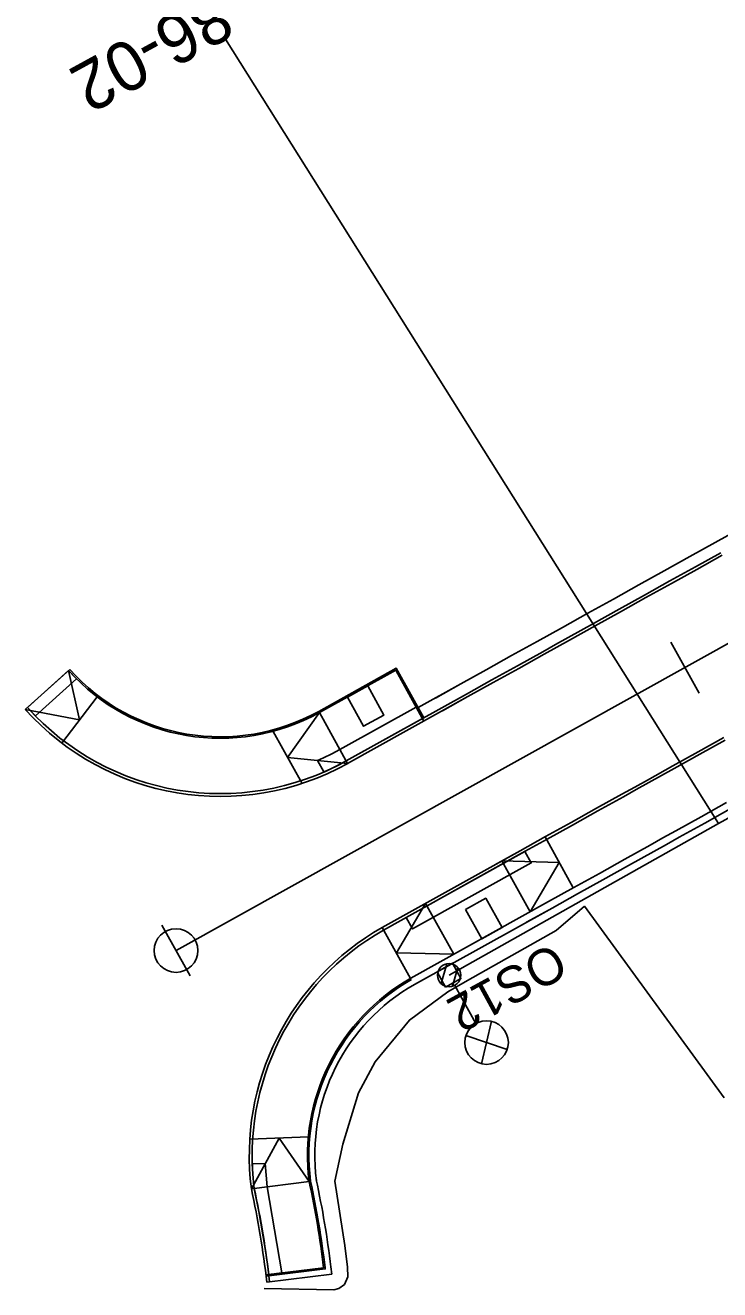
# Model space of a CAD drawing. Extents: x -783978 to -783565, y -1064821 to -1064596.
# Drawn here: x -783977.52 to -783953.66, y -1064775.37 to -1064731.94 of the extents above; entities that cross this region are included whole.
import ezdxf

# ---------------------------------------------------------------- set-up
doc = ezdxf.new("R2010")
doc.units = 0
for name, color, linetype in [('_PS_SO_číslo', 7, 'Continuous'), ('SO 01_50_01', 7, 'Continuous'), ('SO 01_86_02', 7, 'Continuous')]:
    doc.layers.add(name, color=color, linetype=linetype)

msp = doc.modelspace()

# ---------------------------------------------------------------- linework, layer by layer
at = {"layer": '_PS_SO_číslo'}
msp.add_line((-783953.702, -1064759.355), (-783970.636, -1064732.41), dxfattribs=at)
at = {"layer": 'SO 01_50_01'}
for p, q in [((-783972.341, -1064763.721), (-783940.283, -1064745.899)), ((-783953.818, -1064749.705), (-783952.944, -1064749.219)), ((-783953.818, -1064749.705), (-783952.944, -1064749.219)), ((-783953.818, -1064749.705), (-783952.944, -1064749.219)), ((-783954.692, -1064750.191), (-783953.818, -1064749.705)), ((-783954.692, -1064750.191), (-783953.818, -1064749.705)), ((-783954.692, -1064750.191), (-783953.818, -1064749.705)), ((-783954.497, -1064750.541), (-783953.623, -1064750.055)), ((-783955.566, -1064750.677), (-783954.692, -1064750.191)), ((-783955.566, -1064750.677), (-783954.692, -1064750.191)), ((-783955.566, -1064750.677), (-783954.692, -1064750.191)), ((-783955.371, -1064751.027), (-783954.497, -1064750.541)), ((-783954.449, -1064750.627), (-783953.575, -1064750.141)), ((-783954.449, -1064750.628), (-783953.575, -1064750.142)), ((-783956.44, -1064751.163), (-783955.566, -1064750.677)), ((-783956.44, -1064751.163), (-783955.566, -1064750.677)), ((-783956.44, -1064751.163), (-783955.566, -1064750.677)), ((-783955.323, -1064751.113), (-783954.449, -1064750.627)), ((-783955.323, -1064751.114), (-783954.449, -1064750.628)), ((-783957.314, -1064751.649), (-783956.44, -1064751.163)), ((-783957.314, -1064751.649), (-783956.44, -1064751.163)), ((-783957.314, -1064751.649), (-783956.44, -1064751.163)), ((-783956.245, -1064751.512), (-783955.371, -1064751.027)), ((-783956.197, -1064751.599), (-783955.323, -1064751.113)), ((-783956.197, -1064751.6), (-783955.323, -1064751.114)), ((-783958.188, -1064752.135), (-783957.314, -1064751.649)), ((-783958.188, -1064752.135), (-783957.314, -1064751.649)), ((-783958.188, -1064752.135), (-783957.314, -1064751.649)), ((-783957.119, -1064751.998), (-783956.245, -1064751.512)), ((-783957.071, -1064752.085), (-783956.197, -1064751.599)), ((-783957.071, -1064752.086), (-783956.197, -1064751.6)), ((-783959.062, -1064752.621), (-783958.188, -1064752.135)), ((-783959.062, -1064752.621), (-783958.188, -1064752.135)), ((-783959.062, -1064752.621), (-783958.188, -1064752.135)), ((-783957.993, -1064752.484), (-783957.119, -1064751.998)), ((-783957.945, -1064752.571), (-783957.071, -1064752.085)), ((-783957.945, -1064752.572), (-783957.071, -1064752.086)), ((-783959.499, -1064752.863), (-783959.062, -1064752.621)), ((-783959.499, -1064752.863), (-783959.062, -1064752.621)), ((-783959.499, -1064752.863), (-783959.062, -1064752.621)), ((-783958.867, -1064752.97), (-783957.993, -1064752.484)), ((-783958.819, -1064753.057), (-783957.945, -1064752.571)), ((-783958.819, -1064753.058), (-783957.945, -1064752.572)), ((-783960.81, -1064753.592), (-783959.936, -1064753.106)), ((-783960.81, -1064753.592), (-783959.936, -1064753.106)), ((-783960.81, -1064753.592), (-783959.936, -1064753.106)), ((-783959.936, -1064753.106), (-783959.499, -1064752.863)), ((-783959.936, -1064753.106), (-783959.499, -1064752.863)), ((-783959.936, -1064753.106), (-783959.499, -1064752.863)), ((-783959.304, -1064753.213), (-783958.867, -1064752.97)), ((-783959.256, -1064753.3), (-783958.819, -1064753.057)), ((-783959.256, -1064753.3), (-783958.819, -1064753.058)), ((-783954.374, -1064754.877), (-783955.346, -1064753.129)), ((-783961.684, -1064754.078), (-783960.81, -1064753.592)), ((-783961.684, -1064754.078), (-783960.81, -1064753.592)), ((-783961.684, -1064754.078), (-783960.81, -1064753.592)), ((-783960.615, -1064753.942), (-783959.741, -1064753.456)), ((-783960.567, -1064754.028), (-783959.693, -1064753.543)), ((-783960.567, -1064754.029), (-783959.693, -1064753.543)), ((-783959.741, -1064753.456), (-783959.304, -1064753.213)), ((-783959.693, -1064753.543), (-783959.256, -1064753.3)), ((-783959.693, -1064753.543), (-783959.256, -1064753.3)), ((-783961.489, -1064754.428), (-783960.615, -1064753.942)), ((-783961.441, -1064754.514), (-783960.567, -1064754.028)), ((-783961.441, -1064754.515), (-783960.567, -1064754.029)), ((-783962.558, -1064754.564), (-783961.684, -1064754.078)), ((-783962.558, -1064754.564), (-783961.684, -1064754.078)), ((-783962.558, -1064754.564), (-783961.684, -1064754.078)), ((-783962.363, -1064754.914), (-783961.489, -1064754.428)), ((-783964.021, -1064755.378), (-783962.558, -1064754.564)), ((-783963.432, -1064755.05), (-783962.558, -1064754.564)), ((-783963.432, -1064755.05), (-783962.558, -1064754.564)), ((-783962.315, -1064755), (-783961.441, -1064754.514)), ((-783962.315, -1064755.001), (-783961.441, -1064754.515)), ((-783966.492, -1064757.209), (-783962.363, -1064754.914)), ((-783966.444, -1064757.297), (-783962.315, -1064755.001)), ((-783963.189, -1064755.486), (-783962.315, -1064755)), ((-783954.398, -1064756.893), (-783953.524, -1064756.407)), ((-783954.398, -1064756.894), (-783953.524, -1064756.408)), ((-783954.35, -1064756.98), (-783953.476, -1064756.494)), ((-783955.272, -1064757.379), (-783954.398, -1064756.893)), ((-783955.272, -1064757.38), (-783954.398, -1064756.894)), ((-783955.224, -1064757.466), (-783954.35, -1064756.98)), ((-783956.146, -1064757.865), (-783955.272, -1064757.379)), ((-783956.146, -1064757.865), (-783955.272, -1064757.38)), ((-783956.098, -1064757.952), (-783955.224, -1064757.466)), ((-783956.583, -1064758.108), (-783956.146, -1064757.865)), ((-783956.583, -1064758.108), (-783956.146, -1064757.865)), ((-783957.894, -1064758.837), (-783957.02, -1064758.351)), ((-783957.894, -1064758.836), (-783957.02, -1064758.351)), ((-783957.02, -1064758.351), (-783956.583, -1064758.108)), ((-783957.02, -1064758.351), (-783956.583, -1064758.108)), ((-783956.972, -1064758.438), (-783956.535, -1064758.195)), ((-783956.535, -1064758.195), (-783956.098, -1064757.952)), ((-783957.846, -1064758.924), (-783956.972, -1064758.438)), ((-783954.3, -1064759.127), (-783953.426, -1064758.641)), ((-783958.768, -1064759.322), (-783957.894, -1064758.836)), ((-783958.768, -1064759.323), (-783957.894, -1064758.837)), ((-783958.72, -1064759.41), (-783957.846, -1064758.924)), ((-783955.174, -1064759.613), (-783954.3, -1064759.127)), ((-783954.179, -1064759.345), (-783953.305, -1064758.859)), ((-783954.179, -1064759.345), (-783953.305, -1064758.859)), ((-783954.179, -1064759.345), (-783953.305, -1064758.859)), ((-783959.642, -1064759.808), (-783958.768, -1064759.322)), ((-783959.642, -1064759.809), (-783958.768, -1064759.323)), ((-783959.594, -1064759.896), (-783958.72, -1064759.41)), ((-783955.611, -1064759.856), (-783955.174, -1064759.613)), ((-783955.053, -1064759.831), (-783954.179, -1064759.345)), ((-783955.053, -1064759.831), (-783954.179, -1064759.345)), ((-783955.053, -1064759.831), (-783954.179, -1064759.345)), ((-783960.516, -1064760.294), (-783959.642, -1064759.808)), ((-783960.516, -1064760.295), (-783959.642, -1064759.809)), ((-783960.468, -1064760.382), (-783959.594, -1064759.896)), ((-783956.922, -1064760.584), (-783956.048, -1064760.099)), ((-783956.048, -1064760.099), (-783955.611, -1064759.856)), ((-783955.927, -1064760.317), (-783955.49, -1064760.074)), ((-783955.927, -1064760.317), (-783955.49, -1064760.074)), ((-783955.927, -1064760.317), (-783955.49, -1064760.074)), ((-783955.49, -1064760.074), (-783955.053, -1064759.831)), ((-783955.49, -1064760.074), (-783955.053, -1064759.831)), ((-783955.49, -1064760.074), (-783955.053, -1064759.831)), ((-783965.257, -1064762.93), (-783960.516, -1064760.295)), ((-783965.209, -1064763.017), (-783960.468, -1064760.382)), ((-783961.39, -1064760.78), (-783960.516, -1064760.294)), ((-783956.801, -1064760.803), (-783955.927, -1064760.317)), ((-783956.801, -1064760.803), (-783955.927, -1064760.317)), ((-783956.801, -1064760.803), (-783955.927, -1064760.317)), ((-783957.796, -1064761.07), (-783956.922, -1064760.584)), ((-783957.675, -1064761.289), (-783956.801, -1064760.803)), ((-783957.675, -1064761.289), (-783956.801, -1064760.803)), ((-783957.675, -1064761.289), (-783956.801, -1064760.803)), ((-783958.67, -1064761.556), (-783957.796, -1064761.07)), ((-783958.549, -1064761.775), (-783957.675, -1064761.289)), ((-783958.549, -1064761.775), (-783957.675, -1064761.289)), ((-783958.549, -1064761.775), (-783957.675, -1064761.289)), ((-783959.544, -1064762.042), (-783958.67, -1064761.556)), ((-783959.423, -1064762.261), (-783958.549, -1064761.775)), ((-783959.423, -1064762.261), (-783958.549, -1064761.775)), ((-783959.423, -1064762.261), (-783958.549, -1064761.775)), ((-783964.272, -1064764.671), (-783959.544, -1064762.042)), ((-783964.149, -1064764.888), (-783959.423, -1064762.261)), ((-783964.149, -1064764.888), (-783959.423, -1064762.261)), ((-783960.297, -1064762.747), (-783959.423, -1064762.261)), ((-783958.308, -1064762.199), (-783953.511, -1064768.778)), ((-783971.855, -1064764.595), (-783972.827, -1064762.847))]:
    msp.add_line(p, q, dxfattribs=at)
for points in [[(-783967.44, -1064755.505), (-783964.774, -1064754.023), (-783963.824, -1064755.726)], [(-783977.519, -1064755.438), (-783975.992, -1064754.069)], [(-783976.03, -1064754.103), (-783975.659, -1064755.799), (-783977.519, -1064755.438)], [(-783967.416, -1064755.549), (-783964.794, -1064754.091), (-783963.822, -1064755.839)], [(-783976.264, -1064756.595), (-783975.053, -1064755.003)], [(-783967.416, -1064755.549), (-783966.444, -1064757.297), (-783968.506, -1064757.086), (-783967.416, -1064755.549)], [(-783969.003, -1064756.192), (-783968.008, -1064757.981)], [(-783959.663, -1064759.821), (-783958.692, -1064761.568)], [(-783958.308, -1064762.199), (-783959.284, -1064763.028), (-783962.329, -1064764.754), (-783963.005, -1064765.138), (-783964.325, -1064766.112), (-783965.494, -1064767.541), (-783966.077, -1064768.611), (-783966.606, -1064770.378), (-783966.889, -1064771.65), (-783966.536, -1064773.859), (-783966.454, -1064774.598), (-783966.439, -1064774.931), (-783966.549, -1064775.19), (-783966.751, -1064775.336), (-783966.921, -1064775.373), (-783969.315, -1064775.326)], [(-783965.257, -1064762.93), (-783964.285, -1064764.678)], [(-783969.807, -1064770.202), (-783967.795, -1064770.121)], [(-783969.253, -1064774.862), (-783967.269, -1064774.618)], [(-783969.248, -1064774.911), (-783967.213, -1064774.661), (-783967.219, -1064774.612)], [(-783967.02, -1064774.588), (-783966.991, -1064774.836), (-783969.223, -1064775.11)]]:
    msp.add_lwpolyline(points, dxfattribs=at)
for points in [[(-783977.171, -1064755.663), (-783977.445, -1064755.371), (-783976.03, -1064754.103), (-783975.754, -1064754.393)], [(-783966.454, -1064755.014), (-783965.896, -1064756.019), (-783965.196, -1064755.631), (-783965.755, -1064754.626)], [(-783967.258, -1064757.588), (-783967.479, -1064757.193), (-783967.276, -1064757.103), (-783966.99, -1064756.965), (-783966.711, -1064756.816), (-783966.605, -1064756.757), (-783964.089, -1064755.358), (-783963.87, -1064755.752), (-783966.492, -1064757.209), (-783966.713, -1064757.328), (-783966.845, -1064757.395), (-783966.973, -1064757.458), (-783967.172, -1064757.55)], [(-783964.434, -1064762.587), (-783964.216, -1064762.98), (-783960.139, -1064760.714), (-783960.358, -1064760.321)], [(-783961.148, -1064760.646), (-783960.176, -1064762.393), (-783959.178, -1064760.694)], [(-783963.771, -1064762.104), (-783964.771, -1064763.804), (-783962.8, -1064763.852)], [(-783962.397, -1064762.312), (-783961.838, -1064763.317), (-783961.139, -1064762.929), (-783961.698, -1064761.924)], [(-783969.752, -1064771.906), (-783967.768, -1064771.652), (-783968.801, -1064770.162)], [(-783969.154, -1064774.849), (-783968.708, -1064774.795), (-783969.206, -1064771.836), (-783969.276, -1064771.034), (-783969.72, -1064771.048), (-783969.702, -1064771.398), (-783969.662, -1064771.816), (-783969.653, -1064771.893), (-783969.491, -1064772.691), (-783969.275, -1064773.963), (-783969.189, -1064774.575), (-783969.155, -1064774.85)]]:
    msp.add_lwpolyline(points, close=True, dxfattribs=at)
msp.add_circle((-783972.341, -1064763.721), 0.75, dxfattribs=at)
for centre, radius, start, end in [((-783970.817, -1064749.431), 7, 221.8694, 299.0717), ((-783970.817, -1064749.431), 6.95, 221.8694, 299.0717), ((-783970.817, -1064749.431), 9, 221.8694, 299.0717), ((-783970.817, -1064749.431), 8.9, 221.8694, 299.0717), ((-783960.825, -1064770.763), 8.999, 119.5031, 187.2963), ((-783960.825, -1064770.763), 8.899, 119.5031, 187.2963), ((-783960.825, -1064770.763), 6.999, 119.5031, 187.2963), ((-783960.825, -1064770.763), 6.949, 119.5031, 187.2963), ((-783960.825, -1064770.763), 6.749, 119.5031, 187.2963), ((-783998.279, -1064778.313), 31.229, 6.7954, 12.3166), ((-783998.279, -1064778.313), 31.279, 6.7954, 12.3166), ((-783998.279, -1064778.313), 31.479, 6.7954, 12.3166), ((-784002.898, -1064779.019), 33.901, 6.6216, 12.1123), ((-784002.898, -1064779.019), 34.001, 6.6216, 12.1123)]:
    msp.add_arc(centre, radius, start, end, dxfattribs=at)
at = {"layer": 'SO 01_86_02'}
for p, q in [((-783963.038, -1064764.18), (-783963.232, -1064764.86)), ((-783962.659, -1064764.309), (-783962.841, -1064764.947)), ((-783962.037, -1064766.229), (-783962.766, -1064764.918)), ((-783961.506, -1064766.153), (-783961.841, -1064767.612)), ((-783960.965, -1064767.126), (-783962.381, -1064766.64))]:
    msp.add_line(p, q, dxfattribs=at)
msp.add_lwpolyline([(-783878.171, -1064745.018), (-783878.186, -1064744.275), (-783880.673, -1064744.123), (-783888.395, -1064743.656), (-783896.118, -1064743.19), (-783902.642, -1064742.943), (-783906.922, -1064742.781), (-783908.615, -1064742.797), (-783910.308, -1064742.813), (-783914.084, -1064743.083), (-783917.528, -1064743.556), (-783921.591, -1064744.335), (-783924.038, -1064744.952), (-783925.195, -1064745.304), (-783928.174, -1064746.293), (-783932.665, -1064748.008), (-783936.408, -1064749.851), (-783943.728, -1064753.874), (-783953.702, -1064759.355), (-783962.96, -1064764.568)], dxfattribs=at)
msp.add_lwpolyline([(-783963.079, -1064764.975), (-783962.553, -1064764.687), (-783962.841, -1064764.161), (-783963.367, -1064764.449)], close=True, dxfattribs=at)
for centre, radius in [((-783962.96, -1064764.568), 0.4), ((-783961.673, -1064766.883), 0.749)]:
    msp.add_circle(centre, radius, dxfattribs=at)

# ---------------------------------------------------------------- texts
at = {"layer": '_PS_SO_číslo'}
msp.add_text('SO 01-86-02', height=1.7, rotation=208.6817, dxfattribs=at).set_placement((-783964.696, -1064727.259))
at = {"layer": 'SO 01_86_02'}
msp.add_text('OS12', height=1.25, rotation=208.6643, dxfattribs=at).set_placement((-783959.385, -1064763.425))

doc.saveas('drawing.dxf')
